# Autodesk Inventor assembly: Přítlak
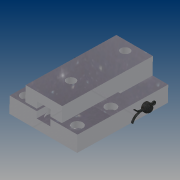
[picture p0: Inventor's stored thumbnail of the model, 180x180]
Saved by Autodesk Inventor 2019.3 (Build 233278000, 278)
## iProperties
Created: 2019-01
Part Number: Přítlak
Material: Všeobecné
Document SubType Name: Assembly
Designer: B-hon
Author: B-hon
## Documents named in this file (6)
- C:\Users\B-hon\OneDrive\Plocha\Bakalářka22\Přítlak\Střední\Přítlak5.iam
- C:\Users\B-hon\OneDrive\Documents\Inventor\Content Center Files\R2019\cs-CZ\BS EN 22 341  B\ISO 2341 - B - 8 x 70BS EN.ipt
- C:\Users\B-hon\OneDrive\Documents\Inventor\Content Center Files\R2019\cs-CZ\CSN EN ISO 1234\CSN EN ISO 1234 - 2x16 x 10 - 9.ipt
- C:\Users\B-hon\OneDrive\Documents\Inventor\Content Center Files\R2019\cs-CZ\CSN EN ISO 2338\ISO 2338 - 6 h8 x 20CSN EN.ipt
- C:\Users\B-hon\OneDrive\Plocha\Bakalářka22\Přítlak\Střední\Příruba desky5.ipt
- C:\Users\B-hon\OneDrive\Plocha\Bakalářka22\Přítlak\Střední\Příruba vozíku5.ipt
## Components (5 placed, 5 different names)
1. BS EN 22341 B B - 8 x 70:1 — Proti sobě:3, Vložit:1
2. CSN EN ISO 1234 2x16:1 — Proti sobě:3
3. CSN EN ISO 2338 6 h8 x 20:1 — Vložit:2
4. Příruba desky5:1 — Vložit:2, Vložit:3, Úhel:1
5. Příruba vozíku5:1 — Vložit:1, Vložit:3, Úhel:1
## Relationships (5: Insert 3, Mate 1, Angle 1)
- Proti sobě:3 [Mate]: BS EN 22341 B B - 8 x 70:1 ↔ CSN EN ISO 1234 2x16:1
- Vložit:1 [Insert]: BS EN 22341 B B - 8 x 70:1 ↔ Příruba vozíku5:1
- Vložit:2 [Insert]: CSN EN ISO 2338 6 h8 x 20:1 ↔ Příruba desky5:1
- Vložit:3 [Insert]: Příruba desky5:1 ↔ Příruba vozíku5:1
- Úhel:1 [Angle]: Příruba desky5:1 ↔ Příruba vozíku5:1
